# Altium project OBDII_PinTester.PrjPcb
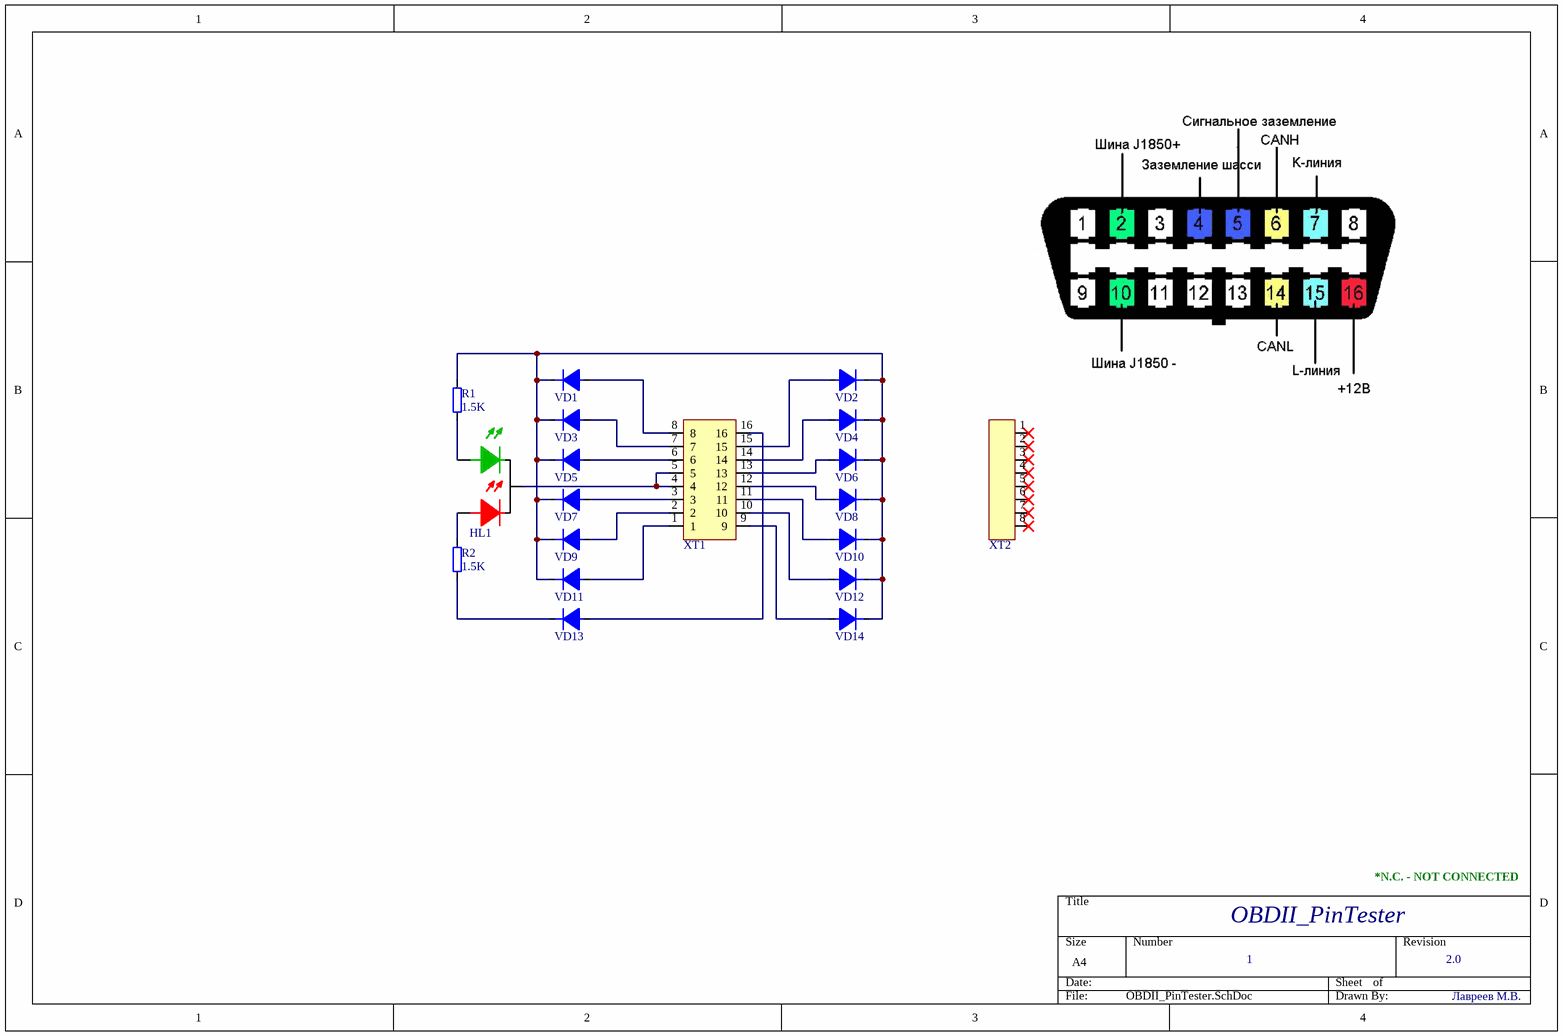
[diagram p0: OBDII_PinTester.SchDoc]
1 sheet, 19 parts. Net scope: global (net labels, ports and power ports of the same name join across sheets).
Board file: OBDII_PinTester.PcbDoc

## Sheet OBDII_PinTester.SchDoc
size A4

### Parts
HL1  LED_RG  [LED_5mm_3pins_R]  (value not drawn)
R1  1.5K  [RES_0805]
R2  1.5K  [RES_0805]
VD1  *  [SMA]  (value not drawn)
VD2  *  [SMA]  (value not drawn)
VD3  *  [SMA]  (value not drawn)
VD4  *  [SMA]  (value not drawn)
VD5  *  [SMA]  (value not drawn)
VD6  *  [SMA]  (value not drawn)
VD7  *  [SMA]  (value not drawn)
VD8  *  [SMA]  (value not drawn)
VD9  *  [SMA]  (value not drawn)
VD10  *  [SMA]  (value not drawn)
VD11  *  [SMA]  (value not drawn)
VD12  *  [SMA]  (value not drawn)
VD13  *  [SMA]  (value not drawn)
VD14  *  [SMA]  (value not drawn)
XT1  *  [PLD-8_OBD]  (value not drawn)
XT2  *  [PLS-8_SMD]  (value not drawn)

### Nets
NetHL1_1: HL1.1(AR) R2.2
NetHL1_2: HL1.2(C) XT1.4 XT1.5
NetHL1_3: HL1.3(AG) R1.1
NetR1_2: R1.2 VD1.2(C) VD2.2(C) VD3.2(C) VD4.2(C) VD5.2(C) VD6.2(C) VD7.2(C) VD8.2(C) VD9.2(C) VD10.2(C) VD11.2(C) VD12.2(C) VD14.2(C)
NetR2_1: R2.1 VD13.2(C)
NetVD1_1: VD1.1(A) XT1.8
NetVD2_1: VD2.1(A) XT1.15
NetVD3_1: VD3.1(A) XT1.7
NetVD4_1: VD4.1(A) XT1.14
NetVD5_1: VD5.1(A) XT1.6
NetVD6_1: VD6.1(A) XT1.13
NetVD7_1: VD7.1(A) XT1.3
NetVD8_1: VD8.1(A) XT1.12
NetVD9_1: VD9.1(A) XT1.2
NetVD10_1: VD10.1(A) XT1.11
NetVD11_1: VD11.1(A) XT1.1
NetVD12_1: VD12.1(A) XT1.10
NetVD13_1: VD13.1(A) XT1.16
NetVD14_1: VD14.1(A) XT1.9

Not connected (* = marked no-connect by the designer): XT2 1* 2* 3* 4* 5* 6* 7* 8*

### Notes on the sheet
- *N.C. - NOT CONNECTED
- OBDII_PinTester
- 1
- 2.0
- Лавреев М.В.

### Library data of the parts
HL1 = LED_RG: LED Red + Green Common Cathode
R1 R2 = RES_SMD: Chip Resistor; Tolerance: ±5%
VD1-VD14 = Diode
XT1 = OBDII
XT2 = PLS-8: Header Connector; Number of Positions: 8; Row Spacing: 2.54mm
